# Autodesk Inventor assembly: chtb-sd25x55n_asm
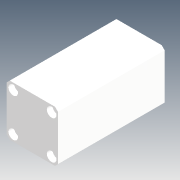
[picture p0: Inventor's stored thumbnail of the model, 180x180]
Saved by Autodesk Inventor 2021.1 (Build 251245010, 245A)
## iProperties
Company: Microsoft
Created: 2018-05
Part Number: chtb-sd25x55n_asm
Description: STEP AP214
Document SubType Name: Assembly
Designer: user
Title: chtb-sd25x55n_asm.STEP
Author: Windows
Revision Number: ÈÎºÎ
Sending System: SolidWorks 2015
Preprocessor: SwSTEP 2.0
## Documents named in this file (4)
- D:\Vault_2016\Projekty\Clamptek\Hydraulic\CHTB\CHTB-25\Inventor\chtb-sd25x55n\chtb-sd25x55n_asm.iam
- D:\Vault_2016\Projekty\Clamptek\Hydraulic\CHTB\CHTB-25\Inventor\chtb-sd25x55n\CHTB-25QG.ipt
- D:\Vault_2016\Projekty\Clamptek\Hydraulic\CHTB\CHTB-25\Inventor\chtb-sd25x55n\CHTB-SD25X55NBT.ipt
- D:\Vault_2016\Projekty\Clamptek\Hydraulic\CHTB\CHTB-25\Inventor\chtb-sd25x55n\CHTB-SD25X55NHSG.ipt
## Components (3 placed, 3 different names)
1. CHTB-25QG_1
2. CHTB-SD25X55NBT_2
3. CHTB-SD25X55NHSG_3
